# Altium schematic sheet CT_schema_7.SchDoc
size 274 x 160 mm
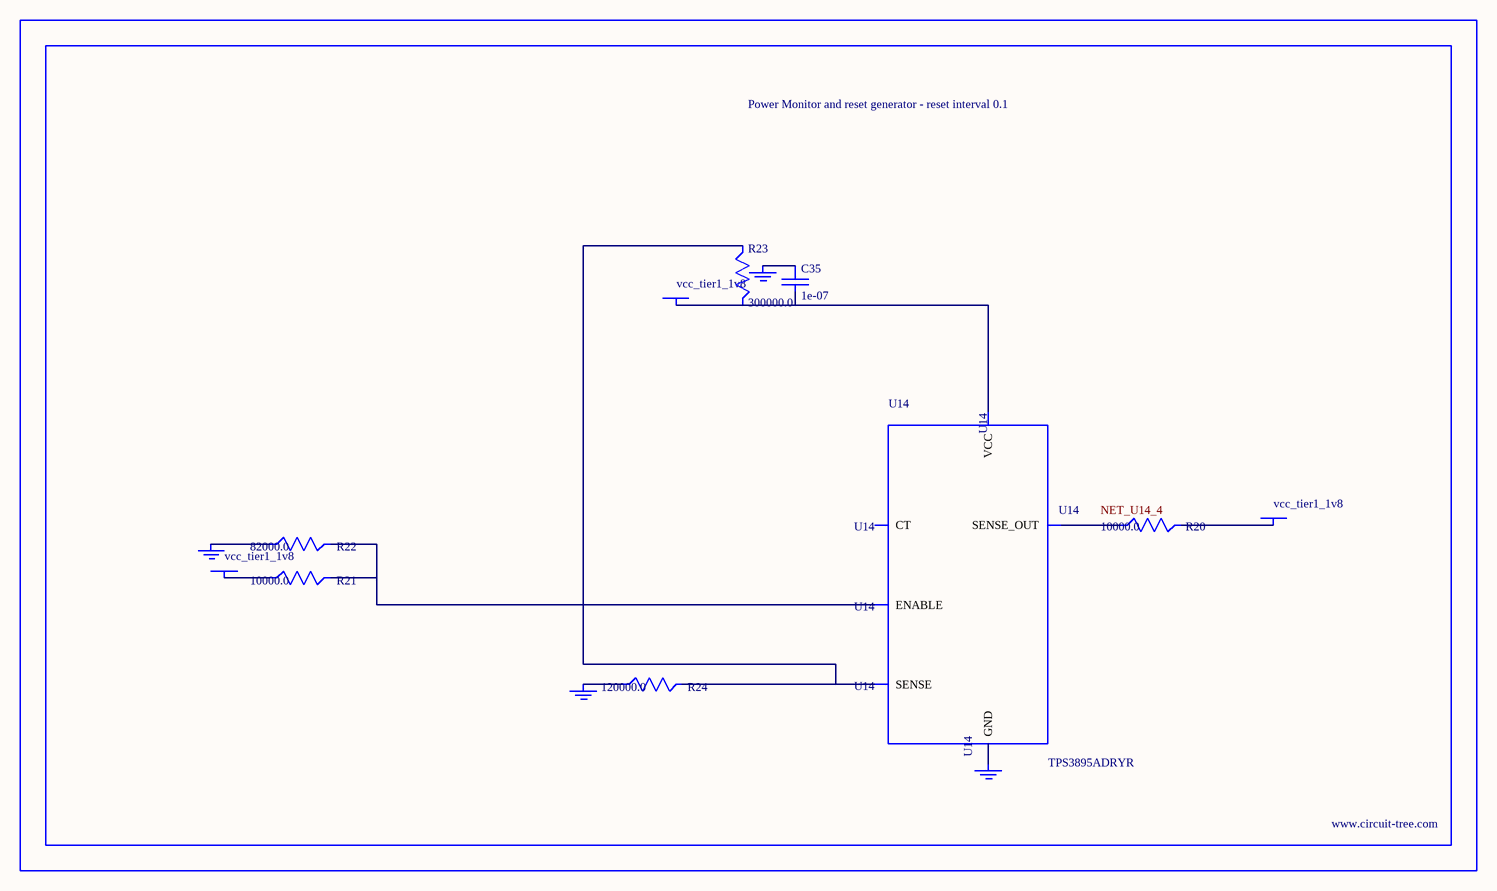
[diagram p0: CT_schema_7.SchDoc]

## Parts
BORDER6  (no value)
C35  1e-07  [C0402]
GND_INSTANCE_6_0  (no value)
GND_INSTANCE_6_1  (no value)
GND_INSTANCE_6_2  (no value)
GND_INSTANCE_6_3  (no value)
POWER_INSTANCE_6_0  vcc_tier1_1v8
POWER_INSTANCE_6_1  vcc_tier1_1v8
POWER_INSTANCE_6_2  vcc_tier1_1v8
R20  10000.0  [R0603]
R21  10000.0  [R0603]
R22  82000.0  [R0603]
R23  300000.0  [R0603]
R24  120000.0  [R0603]
U14  TPS3895ADRYR  [SON-6]

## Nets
NetC35_1: C35.1 GND_INSTANCE_6_2.0(GND)
NetC35_2: C35.2 POWER_INSTANCE_6_2.0(PWR) R23.2 U14.6(VCC)
NetGND_INSTANCE_6_0_0: GND_INSTANCE_6_0.0(GND) R22.1
NetGND_INSTANCE_6_1_0: GND_INSTANCE_6_1.0(GND) R24.1
NetGND_INSTANCE_6_3_0: GND_INSTANCE_6_3.0(GND) U14.2(GND)
NetPOWER_INSTANCE_6_0_0: POWER_INSTANCE_6_0.0(PWR) R21.1
NetPOWER_INSTANCE_6_1_0: POWER_INSTANCE_6_1.0(PWR) R20.2
NetR20_1: R20.1 U14.4(SENSE_OUT)
NetR21_2: R21.2 R22.2 U14.1(ENABLE)
NetR23_1: R23.1 R24.2 U14.3(SENSE)

Not connected (* = marked no-connect by the designer): U14 5(CT)

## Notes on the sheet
- Labels drawn without touching a wire or pin: NET_U14_4

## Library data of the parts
BORDER6 = BORDER_PAGE6
C35 = C0402C104K3RACTU
GND_INSTANCE_6_0-GND_INSTANCE_6_3 = GND
POWER_INSTANCE_6_0-POWER_INSTANCE_6_2 = PWR
R20 R21 = RC0603JR-0710KL
R22 = RC0603JR-0782KL
R23 = RC0603JR-07300KL
R24 = RC0603JR-07120KL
